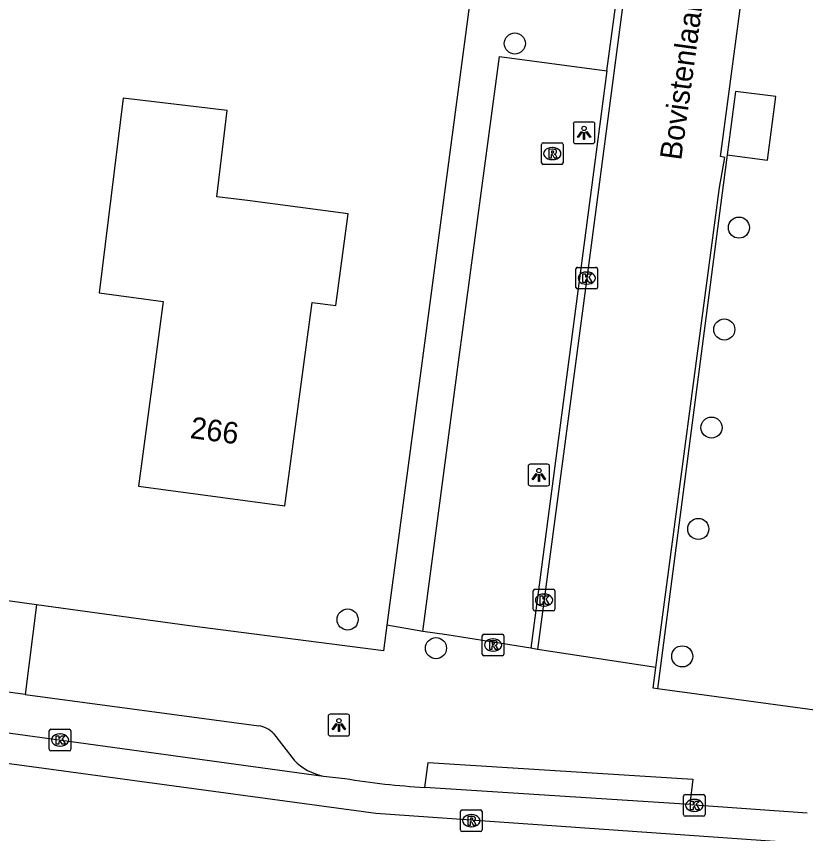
# Model space of a CAD drawing. Extents: x 161696 to 162377, y 380761 to 381673.
# Drawn here: x 162136.47 to 162173.03, y 380788.04 to 380825.9 of the extents above; entities that cross this region are included whole.
import ezdxf

# ---------------------------------------------------------------- set-up
doc = ezdxf.new("R2010")
doc.units = 0
for name, color, linetype in [('IMGEO_Boom', 7, 'Continuous'), ('IMGEO_Hek', 7, 'Continuous'), ('IMGEO_Kolk', 7, 'Continuous'), ('IMGEO_Lichtpunt', 7, 'Continuous'), ('IMGEO_Openbare_ruimte_label', 7, 'Continuous'), ('IMGEO_Pand', 7, 'Continuous'), ('IMGEO_Pand_nummerreeks', 7, 'Continuous'), ('IMGEO_Rijbaan_lokaal_gesloten', 7, 'Continuous'), ('IMGEO_Rijbaan_lokaal_open', 7, 'Continuous'), ('IMGEO_Rioolput', 7, 'Continuous'), ('IMGEO_Voetpad_open', 7, 'Continuous')]:
    doc.layers.add(name, color=color, linetype=linetype)

msp = doc.modelspace()

# ---------------------------------------------------------------- linework, layer by layer
at = {"layer": 'IMGEO_Boom'}
for centre in [(162159.558, 380824.639), (162169.936, 380816.111), (162169.259, 380811.393), (162168.667, 380806.851), (162168.053, 380802.156), (162151.814, 380797.959), (162155.905, 380796.635), (162167.311, 380796.253)]:
    msp.add_circle(centre, 0.489, dxfattribs=at)
at = {"layer": 'IMGEO_Hek'}
for points in [[(162169.394, 380819.478), (162169.133, 380817.486)], [(162169.133, 380817.486), (162166.17, 380794.752)]]:
    msp.add_lwpolyline(points, dxfattribs=at)
at = {"layer": 'IMGEO_Kolk'}
for p, q in [((162162.389, 380813.346), (162162.389, 380814.198)), ((162162.464, 380814.272), (162163.316, 380814.272)), ((162163.39, 380814.198), (162163.39, 380813.346)), ((162162.877, 380814.052), (162162.902, 380814.052)), ((162162.9, 380813.492), (162162.875, 380813.492)), ((162163.316, 380813.272), (162162.464, 380813.272)), ((162160.484, 380799.362), (162161.336, 380799.362)), ((162160.409, 380798.436), (162160.409, 380799.288)), ((162160.897, 380799.142), (162160.922, 380799.142)), ((162161.41, 380799.288), (162161.41, 380798.436)), ((162161.336, 380798.362), (162160.484, 380798.362)), ((162160.92, 380798.582), (162160.895, 380798.582)), ((162137.998, 380791.954), (162137.998, 380792.806)), ((162138.073, 380792.88), (162138.925, 380792.88)), ((162138.486, 380792.66), (162138.511, 380792.66)), ((162138.999, 380792.806), (162138.999, 380791.954)), ((162138.925, 380791.88), (162138.073, 380791.88)), ((162138.509, 380792.1), (162138.484, 380792.1)), ((162167.37, 380788.926), (162167.37, 380789.778)), ((162167.445, 380789.852), (162168.297, 380789.852)), ((162167.858, 380789.632), (162167.883, 380789.632)), ((162168.371, 380789.778), (162168.371, 380788.926)), ((162168.297, 380788.852), (162167.445, 380788.852)), ((162167.881, 380789.072), (162167.856, 380789.072))]:
    msp.add_line(p, q, dxfattribs=at)
for points in [[(162162.389, 380813.346), (162162.389, 380814.198)], [(162162.464, 380814.272), (162163.316, 380814.272)], [(162163.39, 380814.198), (162163.39, 380813.346)], [(162162.71, 380813.972), (162162.833, 380813.972), (162162.833, 380813.821), (162162.963, 380813.972), (162163.127, 380813.972), (162162.981, 380813.821), (162163.134, 380813.572), (162162.982, 380813.572), (162162.897, 380813.736), (162162.833, 380813.669), (162162.833, 380813.572), (162162.71, 380813.572), (162162.71, 380813.972)], [(162163.316, 380813.272), (162162.464, 380813.272)], [(162160.484, 380799.362), (162161.336, 380799.362)], [(162160.409, 380798.436), (162160.409, 380799.288)], [(162160.73, 380799.062), (162160.853, 380799.062), (162160.853, 380798.911), (162160.983, 380799.062), (162161.147, 380799.062), (162161.001, 380798.911), (162161.154, 380798.662), (162161.002, 380798.662), (162160.917, 380798.826), (162160.853, 380798.759), (162160.853, 380798.662), (162160.73, 380798.662), (162160.73, 380799.062)], [(162161.41, 380799.288), (162161.41, 380798.436)], [(162161.336, 380798.362), (162160.484, 380798.362)], [(162137.998, 380791.954), (162137.998, 380792.806)], [(162138.073, 380792.88), (162138.925, 380792.88)], [(162138.319, 380792.58), (162138.442, 380792.58), (162138.442, 380792.429), (162138.572, 380792.58), (162138.736, 380792.58), (162138.59, 380792.429), (162138.743, 380792.18), (162138.591, 380792.18), (162138.506, 380792.344), (162138.442, 380792.277), (162138.442, 380792.18), (162138.319, 380792.18), (162138.319, 380792.58)], [(162138.999, 380792.806), (162138.999, 380791.954)], [(162138.925, 380791.88), (162138.073, 380791.88)], [(162167.37, 380788.926), (162167.37, 380789.778)], [(162167.445, 380789.852), (162168.297, 380789.852)], [(162167.691, 380789.552), (162167.814, 380789.552), (162167.814, 380789.401), (162167.944, 380789.552), (162168.108, 380789.552), (162167.962, 380789.401), (162168.115, 380789.152), (162167.963, 380789.152), (162167.878, 380789.316), (162167.814, 380789.249), (162167.814, 380789.152), (162167.691, 380789.152), (162167.691, 380789.552)], [(162168.371, 380789.778), (162168.371, 380788.926)], [(162168.297, 380788.852), (162167.445, 380788.852)]]:
    msp.add_lwpolyline(points, dxfattribs=at)
for centre, start, end in [((162162.466, 380814.196), 91.552, 178.448), ((162162.466, 380814.196), 91.552, 178.448), ((162163.314, 380814.196), 1.552, 88.448), ((162163.314, 380814.196), 1.552, 88.448), ((162162.466, 380813.348), 181.552, 268.448), ((162162.466, 380813.348), 181.552, 268.448), ((162163.314, 380813.348), 271.552, 358.448), ((162163.314, 380813.348), 271.552, 358.448), ((162160.486, 380799.286), 91.552, 178.448), ((162160.486, 380799.286), 91.552, 178.448), ((162161.334, 380799.286), 1.552, 88.448), ((162161.334, 380799.286), 1.552, 88.448), ((162160.486, 380798.438), 181.552, 268.448), ((162160.486, 380798.438), 181.552, 268.448), ((162161.334, 380798.438), 271.552, 358.448), ((162161.334, 380798.438), 271.552, 358.448), ((162138.075, 380792.804), 91.552, 178.448), ((162138.075, 380792.804), 91.552, 178.448), ((162138.923, 380792.804), 1.552, 88.448), ((162138.923, 380792.804), 1.552, 88.448), ((162138.075, 380791.956), 181.552, 268.448), ((162138.075, 380791.956), 181.552, 268.448), ((162138.923, 380791.956), 271.552, 358.448), ((162138.923, 380791.956), 271.552, 358.448), ((162167.447, 380789.776), 91.552, 178.448), ((162167.447, 380789.776), 91.552, 178.448), ((162168.295, 380789.776), 1.552, 88.448), ((162168.295, 380789.776), 1.552, 88.448), ((162167.447, 380788.928), 181.552, 268.448), ((162167.447, 380788.928), 181.552, 268.448), ((162168.295, 380788.928), 271.552, 358.448), ((162168.295, 380788.928), 271.552, 358.448)]:
    msp.add_arc(centre, 0.0765, start, end, dxfattribs=at)
for centre, major_axis, ratio, start_param, end_param in [((162162.876, 380813.772), (-0.387, 0.002), 0.722429, 4.712389, 7.853982), ((162162.901, 380813.772), (-0.39, 0.002), 0.717154, 1.570796, 4.712389), ((162160.896, 380798.862), (-0.387, 0.002), 0.722429, 4.712389, 7.853982), ((162160.921, 380798.862), (-0.39, 0.002), 0.717154, 1.570796, 4.712389), ((162138.485, 380792.38), (-0.387, 0.002), 0.722429, 4.712389, 7.853982), ((162138.51, 380792.38), (-0.39, 0.002), 0.717154, 1.570796, 4.712389), ((162167.857, 380789.352), (-0.387, 0.002), 0.722429, 4.712389, 7.853982), ((162167.882, 380789.352), (-0.39, 0.002), 0.717154, 1.570796, 4.712389)]:
    msp.add_ellipse(centre, major_axis=major_axis, ratio=ratio, start_param=start_param, end_param=end_param, dxfattribs=at)
at = {"layer": 'IMGEO_Lichtpunt'}
for p, q in [((162163.17, 380821.001), (162162.362, 380821.001)), ((162163.17, 380821.001), (162162.362, 380821.001)), ((162162.268, 380820.906), (162162.268, 380820.099)), ((162162.268, 380820.906), (162162.268, 380820.099)), ((162163.264, 380820.099), (162163.264, 380820.906)), ((162163.264, 380820.099), (162163.264, 380820.906)), ((162162.362, 380820.005), (162163.17, 380820.005)), ((162162.362, 380820.005), (162163.17, 380820.005)), ((162160.174, 380805.058), (162160.174, 380804.251)), ((162160.174, 380805.058), (162160.174, 380804.251)), ((162161.076, 380805.153), (162160.268, 380805.153)), ((162161.076, 380805.153), (162160.268, 380805.153)), ((162161.17, 380804.251), (162161.17, 380805.058)), ((162161.17, 380804.251), (162161.17, 380805.058)), ((162160.268, 380804.157), (162161.076, 380804.157)), ((162160.268, 380804.157), (162161.076, 380804.157)), ((162150.912, 380793.475), (162150.912, 380792.668)), ((162150.912, 380793.475), (162150.912, 380792.668)), ((162151.814, 380793.57), (162151.006, 380793.57)), ((162151.814, 380793.57), (162151.006, 380793.57)), ((162151.908, 380792.668), (162151.908, 380793.475)), ((162151.908, 380792.668), (162151.908, 380793.475)), ((162151.006, 380792.574), (162151.814, 380792.574)), ((162151.006, 380792.574), (162151.814, 380792.574))]:
    msp.add_line(p, q, dxfattribs=at)
for points in [[(162162.642, 380820.57), (162162.681, 380820.542), (162162.493, 380820.28), (162162.455, 380820.307), (162162.642, 380820.57)], [(162162.854, 380820.542), (162162.892, 380820.569), (162163.079, 380820.307), (162163.04, 380820.279), (162162.854, 380820.542)], [(162162.744, 380820.522), (162162.791, 380820.522), (162162.791, 380820.2), (162162.744, 380820.2), (162162.744, 380820.522)], [(162160.548, 380804.722), (162160.587, 380804.694), (162160.399, 380804.432), (162160.361, 380804.459), (162160.548, 380804.722)], [(162160.65, 380804.674), (162160.697, 380804.674), (162160.697, 380804.352), (162160.65, 380804.352), (162160.65, 380804.674)], [(162160.76, 380804.694), (162160.798, 380804.721), (162160.985, 380804.459), (162160.946, 380804.431), (162160.76, 380804.694)], [(162151.286, 380793.139), (162151.325, 380793.111), (162151.137, 380792.849), (162151.099, 380792.876), (162151.286, 380793.139)], [(162151.388, 380793.091), (162151.435, 380793.091), (162151.435, 380792.769), (162151.388, 380792.769), (162151.388, 380793.091)], [(162151.498, 380793.111), (162151.536, 380793.138), (162151.723, 380792.876), (162151.684, 380792.848), (162151.498, 380793.111)]]:
    msp.add_lwpolyline(points, dxfattribs=at)
for centre in [(162162.767, 380820.704), (162160.673, 380804.856), (162151.411, 380793.273)]:
    msp.add_circle(centre, 0.0994, dxfattribs=at)
for centre, start, end in [((162162.362, 380820.906), 90, 180), ((162162.362, 380820.906), 90, 180), ((162163.17, 380820.906), 0, 90), ((162163.17, 380820.906), 0, 90), ((162162.362, 380820.099), 180, 270), ((162162.362, 380820.099), 180, 270), ((162163.17, 380820.099), 270, 0), ((162163.17, 380820.099), 270, 360), ((162160.268, 380805.058), 90, 180), ((162160.268, 380805.058), 90, 180), ((162161.076, 380805.058), 0, 90), ((162161.076, 380805.058), 0, 90), ((162160.268, 380804.251), 180, 270), ((162160.268, 380804.251), 180, 270), ((162161.076, 380804.251), 270, 0), ((162161.076, 380804.251), 270, 360), ((162151.006, 380793.475), 90, 180), ((162151.006, 380793.475), 90, 180), ((162151.814, 380793.475), 0, 90), ((162151.814, 380793.475), 0, 90), ((162151.006, 380792.668), 180, 270), ((162151.006, 380792.668), 180, 270), ((162151.814, 380792.668), 270, 0), ((162151.814, 380792.668), 270, 360)]:
    msp.add_arc(centre, 0.0946, start, end, dxfattribs=at)
at = {"layer": 'IMGEO_Pand'}
for points in [[(162147.173, 380817.373), (162145.765, 380817.54), (162146.238, 380821.532), (162141.421, 380822.102), (162140.313, 380813.096), (162143.277, 380812.697), (162142.793, 380809.1), (162142.126, 380804.144), (162148.908, 380803.232), (162150.175, 380812.651), (162151.265, 380812.504), (162151.836, 380816.746), (162147.173, 380817.373)], [(162171.651, 380822.178), (162169.781, 380822.423), (162169.394, 380819.478), (162171.265, 380819.233), (162171.651, 380822.178)]]:
    msp.add_lwpolyline(points, dxfattribs=at)
at = {"layer": 'IMGEO_Rijbaan_lokaal_gesloten'}
for points in [[(162234.771, 380780.432), (162229.289, 380780.178), (162226.418, 380780.403), (162192.055, 380785.129), (162178.941, 380786.895), (162173.589, 380787.538), (162153.114, 380788.982), (161814.137, 380834.931)], [(162050.672, 380804.267), (162117.084, 380795.318), (162150.704, 380790.709)], [(162150.704, 380790.709), (162151.69, 380790.598)], [(162167.669, 380789.389), (162155.394, 380790.188)], [(162167.669, 380789.389), (162173.094, 380789.008)]]:
    msp.add_lwpolyline(points, dxfattribs=at)
msp.add_arc((162157.332, 380824.632), 34.499, 260.5875, 266.7797, dxfattribs=at)
at = {"layer": 'IMGEO_Rijbaan_lokaal_open'}
for points in [[(162169.299, 380861.974), (162168.858, 380858.73), (162166.771, 380843.001), (162164.647, 380827.166), (162164.147, 380823.285), (162162.89, 380813.772), (162160.607, 380796.577)], [(162163.821, 380823.369), (162165.731, 380837.514)], [(162163.821, 380823.369), (162160.296, 380796.631)], [(162160.607, 380796.577), (162160.296, 380796.631)]]:
    msp.add_lwpolyline(points, dxfattribs=at)
at = {"layer": 'IMGEO_Rioolput'}
for p, q in [((162160.794, 380819.113), (162160.794, 380819.965)), ((162160.869, 380820.039), (162161.721, 380820.039)), ((162161.282, 380819.819), (162161.307, 380819.819)), ((162161.795, 380819.965), (162161.795, 380819.113)), ((162161.305, 380819.259), (162161.28, 380819.259)), ((162161.721, 380819.039), (162160.869, 380819.039)), ((162158.051, 380796.355), (162158.051, 380797.207)), ((162158.126, 380797.281), (162158.978, 380797.281)), ((162159.052, 380797.207), (162159.052, 380796.355)), ((162158.539, 380797.061), (162158.564, 380797.061)), ((162158.562, 380796.501), (162158.537, 380796.501)), ((162158.978, 380796.281), (162158.126, 380796.281)), ((162157.117, 380789.143), (162157.969, 380789.143)), ((162157.042, 380788.217), (162157.042, 380789.069)), ((162157.53, 380788.923), (162157.555, 380788.923)), ((162158.043, 380789.069), (162158.043, 380788.217)), ((162157.969, 380788.143), (162157.117, 380788.143)), ((162157.553, 380788.363), (162157.528, 380788.363))]:
    msp.add_line(p, q, dxfattribs=at)
for points in [[(162160.794, 380819.113), (162160.794, 380819.965)], [(162160.869, 380820.039), (162161.721, 380820.039)], [(162161.795, 380819.965), (162161.795, 380819.113)], [(162161.383, 380819.737), (162161.131, 380819.739), (162161.131, 380819.339)], [(162161.131, 380819.339), (162161.255, 380819.339), (162161.255, 380819.501), (162161.266, 380819.501)], [(162161.309, 380819.658), (162161.255, 380819.658), (162161.255, 380819.577)], [(162161.255, 380819.577), (162161.307, 380819.577)], [(162161.313, 380819.472), (162161.384, 380819.339), (162161.524, 380819.339), (162161.459, 380819.465)], [(162161.721, 380819.039), (162160.869, 380819.039)], [(162158.051, 380796.355), (162158.051, 380797.207)], [(162158.126, 380797.281), (162158.978, 380797.281)], [(162159.052, 380797.207), (162159.052, 380796.355)], [(162158.64, 380796.979), (162158.388, 380796.981), (162158.388, 380796.581)], [(162158.388, 380796.581), (162158.512, 380796.581), (162158.512, 380796.743), (162158.523, 380796.743)], [(162158.566, 380796.9), (162158.512, 380796.9), (162158.512, 380796.819)], [(162158.512, 380796.819), (162158.564, 380796.819)], [(162158.57, 380796.714), (162158.641, 380796.581), (162158.781, 380796.581), (162158.716, 380796.707)], [(162158.978, 380796.281), (162158.126, 380796.281)], [(162157.117, 380789.143), (162157.969, 380789.143)], [(162157.042, 380788.217), (162157.042, 380789.069)], [(162157.631, 380788.841), (162157.379, 380788.843), (162157.379, 380788.443)], [(162157.557, 380788.762), (162157.503, 380788.762), (162157.503, 380788.681)], [(162158.043, 380789.069), (162158.043, 380788.217)], [(162157.379, 380788.443), (162157.503, 380788.443), (162157.503, 380788.605), (162157.514, 380788.605)], [(162157.503, 380788.681), (162157.555, 380788.681)], [(162157.561, 380788.576), (162157.632, 380788.443), (162157.772, 380788.443), (162157.707, 380788.569)], [(162157.969, 380788.143), (162157.117, 380788.143)]]:
    msp.add_lwpolyline(points, dxfattribs=at)
for centre, radius, start, end in [((162160.871, 380819.963), 0.0765, 91.552, 178.448), ((162160.871, 380819.963), 0.0765, 91.552, 178.448), ((162161.719, 380819.963), 0.0765, 1.552, 88.448), ((162161.719, 380819.963), 0.0765, 1.552, 88.448), ((162161.265, 380819.448), 0.0533, 26.0293, 88.6989), ((162161.291, 380819.766), 0.19, 274.7715, 282.9687), ((162161.315, 380819.562), 0.0964, 77.0061, 93.1865), ((162161.329, 380819.619), 0.0378, 276.6634, 79.6772), ((162161.382, 380819.627), 0.109, 350.3612, 89.416), ((162161.38, 380819.627), 0.112, 277.5842, 350.9817), ((162161.364, 380819.412), 0.108, 29.5134, 73.7905), ((162160.871, 380819.115), 0.0765, 181.552, 268.448), ((162160.871, 380819.115), 0.0765, 181.552, 268.448), ((162161.719, 380819.115), 0.0765, 271.552, 358.448), ((162161.719, 380819.115), 0.0765, 271.552, 358.448), ((162158.128, 380797.205), 0.0765, 91.552, 178.448), ((162158.128, 380797.205), 0.0765, 91.552, 178.448), ((162158.976, 380797.205), 0.0765, 1.552, 88.448), ((162158.976, 380797.205), 0.0765, 1.552, 88.448), ((162158.522, 380796.69), 0.0533, 26.0293, 88.6989), ((162158.548, 380797.008), 0.19, 274.7715, 282.9687), ((162158.572, 380796.804), 0.0964, 77.0061, 93.1865), ((162158.586, 380796.861), 0.0378, 276.6634, 79.6772), ((162158.639, 380796.869), 0.109, 350.3612, 89.416), ((162158.637, 380796.869), 0.112, 277.5842, 350.9817), ((162158.621, 380796.654), 0.108, 29.5134, 73.7905), ((162158.128, 380796.357), 0.0765, 181.552, 268.448), ((162158.128, 380796.357), 0.0765, 181.552, 268.448), ((162158.976, 380796.357), 0.0765, 271.552, 358.448), ((162158.976, 380796.357), 0.0765, 271.552, 358.448), ((162157.119, 380789.067), 0.0765, 91.552, 178.448), ((162157.119, 380789.067), 0.0765, 91.552, 178.448), ((162157.967, 380789.067), 0.0765, 1.552, 88.448), ((162157.967, 380789.067), 0.0765, 1.552, 88.448), ((162157.563, 380788.666), 0.0964, 77.0061, 93.1865), ((162157.577, 380788.723), 0.0378, 276.6634, 79.6772), ((162157.63, 380788.731), 0.109, 350.3612, 89.416), ((162157.513, 380788.552), 0.0533, 26.0293, 88.6989), ((162157.539, 380788.87), 0.19, 274.7715, 282.9687), ((162157.628, 380788.731), 0.112, 277.5842, 350.9817), ((162157.612, 380788.516), 0.108, 29.5134, 73.7905), ((162157.119, 380788.219), 0.0765, 181.552, 268.448), ((162157.119, 380788.219), 0.0765, 181.552, 268.448), ((162157.967, 380788.219), 0.0765, 271.552, 358.448), ((162157.967, 380788.219), 0.0765, 271.552, 358.448)]:
    msp.add_arc(centre, radius, start, end, dxfattribs=at)
for centre, major_axis, ratio, start_param, end_param in [((162161.281, 380819.539), (-0.387, 0.002), 0.722429, 4.712389, 7.853982), ((162161.306, 380819.539), (-0.39, 0.002), 0.717154, 1.570796, 4.712389), ((162158.538, 380796.781), (-0.387, 0.002), 0.722429, 4.712389, 7.853982), ((162158.563, 380796.781), (-0.39, 0.002), 0.717154, 1.570796, 4.712389), ((162157.529, 380788.643), (-0.387, 0.002), 0.722429, 4.712389, 7.853982), ((162157.554, 380788.643), (-0.39, 0.002), 0.717154, 1.570796, 4.712389)]:
    msp.add_ellipse(centre, major_axis=major_axis, ratio=ratio, start_param=start_param, end_param=end_param, dxfattribs=at)
at = {"layer": 'IMGEO_Voetpad_open'}
for points in [[(162162.074, 380861.396), (162160.671, 380850.541), (162158.567, 380834.74), (162157.414, 380826.104), (162155.381, 380810.759), (162153.632, 380797.692)], [(162166.095, 380795.737), (162169.037, 380817.977), (162169.282, 380819.362), (162169.081, 380819.4), (162170.876, 380832.862), (162171.035, 380832.837), (162171.268, 380834.658)], [(162155.305, 380797.409), (162156.978, 380810.115), (162158.849, 380824.039), (162163.821, 380823.369)], [(162137.41, 380798.647), (162133.183, 380799.23)], [(162137.41, 380798.647), (162136.88, 380794.488)], [(162153.632, 380797.692), (162153.473, 380796.508), (162144.486, 380797.672), (162137.41, 380798.647)], [(162155.305, 380797.409), (162153.632, 380797.692)], [(162160.296, 380796.631), (162156.416, 380797.255), (162155.305, 380797.409)], [(162166.095, 380795.737), (162160.607, 380796.577)], [(162246.56, 380789.741), (162242.108, 380784.149), (162233.587, 380785.305), (162203.847, 380789.736), (162189.165, 380791.629), (162166.17, 380794.752), (162165.968, 380794.779), (162166.095, 380795.737)], [(162136.88, 380794.488), (162132.637, 380795.06)], [(162136.88, 380794.488), (162147.7, 380793.031)], [(162148.387, 380792.674), (162149.337, 380791.452)], [(162155.394, 380790.188), (162155.551, 380791.338), (162167.803, 380790.565), (162167.669, 380789.389)]]:
    msp.add_lwpolyline(points, dxfattribs=at)
for centre, radius, start, end in [((162147.553, 380791.908), 1.133, 42.5553, 82.5273), ((162151.142, 380793.144), 2.474, 223.1463, 259.8033)]:
    msp.add_arc(centre, radius, start, end, dxfattribs=at)

# ---------------------------------------------------------------- texts
at = {"layer": 'IMGEO_Openbare_ruimte_label'}
msp.add_text('Bovistenlaan', height=1, rotation=82.1858, dxfattribs=at).set_placement((162167.259, 380819.202))
at = {"layer": 'IMGEO_Pand_nummerreeks'}
msp.add_text('266', height=1, rotation=352.3412, dxfattribs=at).set_placement((162144.486, 380806.37))

doc.saveas('drawing.dxf')
